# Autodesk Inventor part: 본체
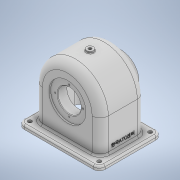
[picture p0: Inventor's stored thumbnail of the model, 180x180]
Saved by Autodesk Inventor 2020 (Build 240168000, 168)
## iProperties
Created: 2022-09
Part Number: 본체
Material: 일반
Document SubType Name: Modeling
Designer: Administrator
Density: 1 g/cm^3
Appearance: 기본값
Mass: 987.342 g
Surface Area: 1165.69 cm^2
Volume: 365.682 cm^3
Author: Administrator
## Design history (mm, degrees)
sketch "스케치1"
  geometry: L1 (-60, 54)-(60, 54); L2 (70, 44)-(70, -44); L3 (60, -54)-(-60, -54); L4 (-70, -44)-(-70, 44); C1 r 3.3 at (-60, 44); C2 r 3.3 at (60, 44); C3 r 3.3 at (60, -44); C4 r 3.3 at (-60, -44); A1 r 10 centre (-60, 44) between (-60, 54) and (-70, 44); A2 r 10 centre (-60, -44) between (-70, -44) and (-60, -54); A3 r 10 centre (60, -44) between (60, -54) and (70, -44); A4 r 10 centre (60, 44) between (70, 44) and (60, 54); 4 further points
  constraints: 8 centre point, 8 end point, 8 point on circle, 8 tangent, 6 point on line, 4 coincident, 3 equal radius, 2 parallel, 1 horizontal, 1 perpendicular
  dimensions: "d0" = 140 distance of point (70, -54) point (-70, -54); "d1" = 108 distance of point (70, 54) point (70, -54); "d2" = 10 radius of A1; "d3" = 6.6 diameter of C1; "d4" = 6.6 diameter of C2; "d5" = 6.6 diameter of C3; "d6" = 6.6 diameter of C4
extrude "돌출1" new body sketch "스케치1" distance "d7" = 7; taper "d8" = 0 deg
sketch "스케치2"
  geometry: L1 (-60, 0)-(60, 0) reference; L2 (-60, 7)-(60, 7) reference; L3 (-63.3, 7)-(-56.7, 7) reference; L4 (-56.7, 64.001)-(-56.7, 7); L5 (57.3, 64)-(57.3, 5.235); A1 r 57 centre (0.3, 64) between (0.6, 120.999) and (-56.7, 64.001); 2 further points
  constraints: 4 end point, 3 point on circle, 1 centre point, 1 perpendicular, 1 tangent, 1 vertical
  dimensions: "d9" = 57 radius of A1; "d10" = 64 distance from line of L1 A1.centre
extrude "돌출2" new body sketch "스케치2" stored distance "d11" = 78; taper "d12" = 0 deg
feature "쉘1" dims "d13" = 5
sketch "스케치3"
  geometry: L1 (57, 7)-(57, 64.001); L2 (-57, 64)-(-57, 7); L3 (-57, 7)-(57, 7); L4 (-60, 0)-(60, 0) reference; C1 r 32 at (0, 64); A1 r 57 centre (0, 64) between (57, 64.001) and (-57, 64); 2 further points
  constraints: 6 end point, 2 centre point, 2 point on circle, 1 coincident, 1 midpoint, 1 vertical alignment
  dimensions: "d14" = 32 radius of C1
sketch "스케치4"
  geometry: C1 r 31 at (-0.3, -64); A1 r 57 centre (-0.3, -64) between (-57.3, -64) and (56.7, -64.001) reference; 1 further point
  constraints: 1 centre point, 1 coincident
  dimensions: "d15" = 62 diameter of C1
extrude "돌출3" join sketch "스케치4" distance "d16" = 15; taper "d17" = 0 deg
feature "결합1"
  node "솔리드2"
sketch "스케치5"
  geometry: C1 r 20 at (0.3, 0); 1 further point
  constraints: 1 centre point
  dimensions: "d18" = 40 diameter of C1
extrude "돌출4" cut sketch "스케치5" distance "d19" = 16; taper "d20" = 0 deg
fillet "모깎기1" dims "d21" = 0.6
sketch "스케치6"
  geometry: C1 r 19.4 at (0, 0) reference; C2 r 17.5 at (0, 0); 1 further point
  constraints: 1 centre point, 1 coincident
  dimensions: "d22" = 35 diameter of C2
extrude "돌출5" cut sketch "스케치6" distance "d23" = 16; taper "d24" = 0 deg
chamfer "모따기1" distance "d25" = 1; stored, may be unused: second distance "d26" = 2, angle "d27" = 45 deg
node "작업 평면1"
sketch "스케치9"
  geometry: L1 (-34, 116)-(-34, 64) reference; L2 (-34, 100.083)-(-20, 92); L3 (-34, 64)-(-34, 12) reference; L4 (-50.325, 64)-(9.78, 64); L5 (-34, 64)-(34, 64) reference; L6 (-20, 92)-(-20, 64); 4 further points
  constraints: 6 end point, 3 point on line, 1 perpendicular
  dimensions: "d35" = 60 deg angle of L6 L2; "d36" = 56 diameter of L2.end L4; "d37" = 14 distance between parallel lines of L1 L6
revolve "회전1" sketch "스케치9" stored, may be unused: angle "d38" = 90 deg
sketch "스케치10"
  geometry: C1 r 28 at (0, 0) reference; C2 r 20 at (0, 0); 1 further point
  constraints: 1 centre point, 1 coincident
  dimensions: "d39" = 40 diameter of C2
extrude "돌출8" cut sketch "스케치10" distance "d40" = 16; taper "d41" = 0 deg
extrude "돌출9" cut sketch "스케치3" stored distance "d42" = 3.25; taper "d43" = 0 deg
fillet "모깎기2" dims "d44" = 14
fillet "모깎기3" dims "d45" = 3
node "작업 평면2"
node "작업 평면3"
sketch "스케치12"
  geometry: C1 r 6 at (0, 0); 1 further point
  constraints: 1 centre point, 1 coincident
  dimensions: "d55" = 12 diameter of C1
extrude "돌출10" join sketch "스케치12" stored distance "d56" = 16; taper "d57" = 0 deg; dims "d0" = 140, "d1" = 108, "d2" = 10, "d3" = 6.6, "d4" = 6.6, "d5" = 6.6, "d6" = 6.6, "d10" = 64
fillet "모깎기4" dims "d58" = 1
sketch "스케치13"
  geometry: C1 r 6 at (0, 0) reference; 2 further points
  constraints: 1 coincident
hole "구멍2" sketch "스케치13" at (0, 0) diameter "d59" = 5.1881; stored, may be unused: countersink angle "d63" = 90 deg, drill point angle "d65" = 118 deg; dims "d60" = 12, "d61" = 4, "d62" = 2, "d64" = 16
sketch "스케치14"
  geometry: L1 (0.941, 15.484)-(0.941, 34.516); L2 (0.941, 34.516)-(93.06, 34.516); L3 (93.06, 34.516)-(93.06, 15.484); L4 (93.06, 15.484)-(0.941, 15.484); L5 (0, -14)-(54.001, -14) reference; L6 (64.001, -19)-(64.001, 69) reference; 3 further points
  constraints: 2 midpoint, 2 other
  dimensions: "d66" = 39 distance from line of L5 point (0.941, 25); "d67" = 17 distance from line of L6 point (47.001, 34.516)
feature "엠보싱1" sketch "스케치14" dims "d0" = 140, "d1" = 108, "d2" = 10, "d3" = 6.6, "d4" = 6.6, "d5" = 6.6, "d6" = 6.6, "d68" = 0.5, "d69" = 0
chamfer "모따기2" distance "d70" = 1; stored, may be unused: second distance "d71" = 2, angle "d72" = 45 deg
sketch "스케치16" dims "d84" = 48
  geometry: C1 r 21 at (0, 0) reference; 3 further points
  constraints: 1 coincident, 1 vertical alignment, 2 other
hole "구멍4" sketch "스케치16" at (0, 24) diameter "d85" = 2.459; stored, may be unused: countersink angle "d89" = 90 deg, drill point angle "d91" = 118 deg; dims "d86" = 7, "d87" = 4, "d88" = 2, "d90" = 9
node "작업 평면4"
sketch "스케치17"
  geometry: L1 (-51.7, -34)-(-51.7, 34) reference; L2 (52.3, -34)-(-51.7, -34) reference; L3 (-51.7, 34)-(52.3, 34) reference; L4 (52.3, -34)-(52.3, 34) reference; 1 further point
extrude "돌출11" cut sketch "스케치17" distance "d95" = 14.25; taper "d96" = 0 deg
fillet "모깎기5" dims "d97" = 9
node "솔리드1"
pattern_circular "원형 패턴2" dims angle "d93" = 360 deg
mirror "미러2"
feature "A9D066F2-1C7D-4E18-AEED-F7BC21143FA4" dims "d85" = 2.459, "d86" = 7, "d87" = 4, "d88" = 2, "d89" = 90 deg, "d90" = 9, "d91" = 118 deg
other parameters: "d28" = -14, "d54" = -124
